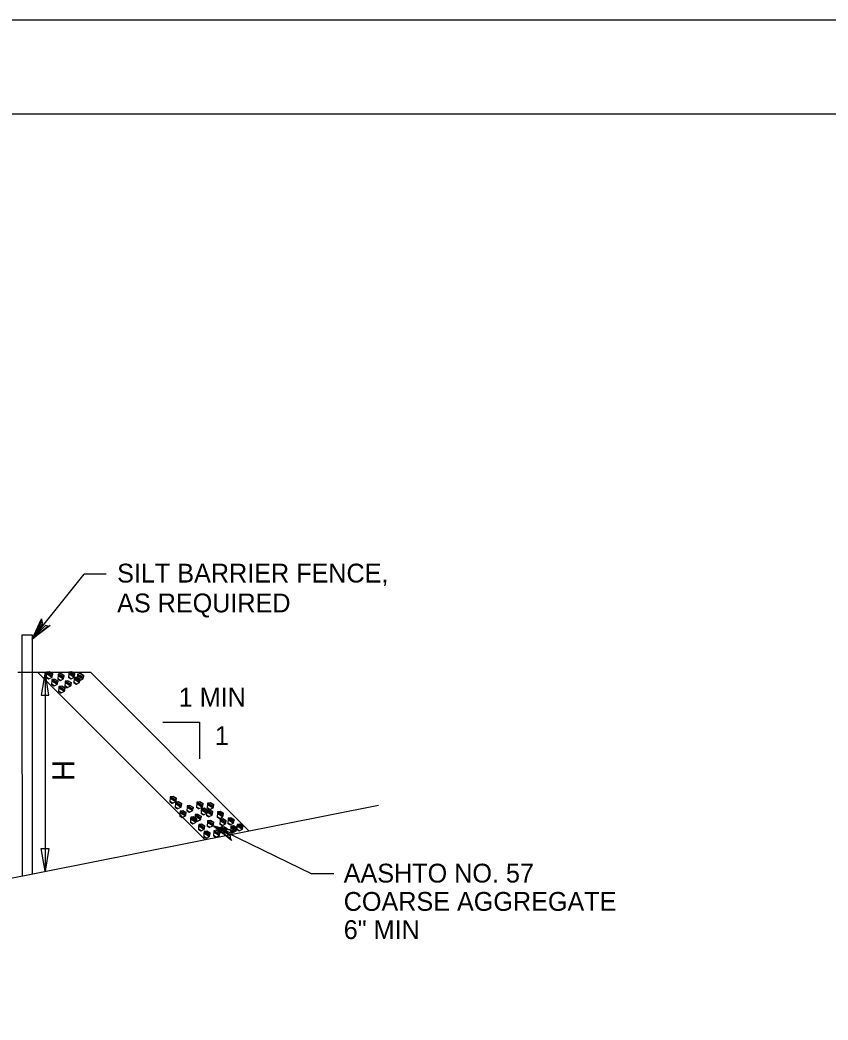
# Model space of a CAD drawing. Extents: x 636462 to 639049, y 299944 to 300538.
# Drawn here: x 637774 to 637902.8, y 300379.2 to 300538.4 of the extents above; entities that cross this region are included whole.
import ezdxf

# ---------------------------------------------------------------- set-up
doc = ezdxf.new("R2010")
doc.units = 0
for name, color, linetype in [('1', 7, 'Continuous'), ('Default', 7, 'Continuous'), ('PLT-BNDY', 7, 'Continuous')]:
    doc.layers.add(name, color=color, linetype=linetype)

msp = doc.modelspace()

# ---------------------------------------------------------------- linework, layer by layer
at = {"layer": '1'}
msp.add_lwpolyline([(638128.91, 299959.45), (638128.91, 300523.45), (637342.91, 300523.45), (637342.91, 299959.45), (638128.91, 299959.45), (638128.91, 299985.81), (637928.91, 299985.81), (637928.91, 300050.49), (638128.91, 300050.49), (638128.91, 300079.45), (637928.91, 300079.45), (637928.91, 299959.45), (638007.72, 299959.45), (638007.72, 299985.81), (638007.72, 299959.45), (638084.72, 299959.45), (638084.72, 299985.81), (638084.72, 299973.49), (638128.91, 299973.49)], dxfattribs=at)
at = {"layer": 'Default'}
for p, q in [((637775.96, 300439.85), (637784.28, 300450.2)), ((637787.77, 300450.2), (637784.28, 300450.2)), ((637774.37, 300440.54), (637775.96, 300440.54)), ((637774.38, 300434.62), (637774.37, 300440.54)), ((637775.96, 300440.54), (637775.96, 300434.66)), ((637773.72, 300434.6), (637785.25, 300434.6)), ((637774.47, 300402.15), (637774.38, 300434.54)), ((637775.96, 300434.55), (637775.96, 300402.48)), ((637776.84, 300434.6), (637803.49, 300407.95)), ((637778.04, 300434.6), (637778.04, 300402.9)), ((637785.25, 300434.6), (637810.51, 300409.34)), ((637718.2, 300391.02), (637831.16, 300413.44)), ((637804.92, 300410.07), (637820.54, 300402.49)), ((637824.04, 300402.49), (637820.54, 300402.49))]:
    msp.add_line(p, q, dxfattribs=at)
for points in [[(637778.5, 300441.95), (637778.84, 300442.02), (637775.96, 300439.85), (637778.5, 300441.95), (637778.09, 300442.03), (637775.96, 300439.85), (637777.68, 300442.36), (637777.5, 300442.74), (637775.96, 300439.85), (637777.48, 300443.12), (637777.5, 300442.74)], [(637796.8, 300426.66), (637802.64, 300426.66), (637802.64, 300420.82)], [(637807.57, 300408.11), (637807.71, 300407.79), (637804.92, 300410.07), (637807.57, 300408.11), (637807.55, 300408.53), (637804.92, 300410.07), (637807.77, 300409), (637808.09, 300409.27), (637804.92, 300410.07), (637808.46, 300409.37), (637808.09, 300409.27)]]:
    msp.add_lwpolyline(points, dxfattribs=at)
for points in [[(637777.43, 300430.96), (637778.64, 300430.96), (637778.04, 300434.6)], [(637778.21, 300433.83), (637778.63, 300433.57), (637779.15, 300433.83), (637778.25, 300434.39)], [(637778.6, 300433.56), (637778.6, 300433.56), (637778.63, 300433.57), (637778.21, 300433.83)], [(637778.25, 300434.39), (637779.15, 300433.83), (637779.19, 300434.03), (637778.27, 300434.6)], [(637778.27, 300434.6), (637779.19, 300434.03), (637779.25, 300434.31), (637778.7, 300434.65)], [(637778.7, 300434.65), (637779.25, 300434.31), (637779.26, 300434.33), (637779.26, 300434.33)], [(637779.11, 300433.25), (637780, 300432.7), (637780.04, 300432.89), (637779.12, 300433.46)], [(637779.12, 300433.46), (637780.04, 300432.89), (637780.1, 300433.18), (637779.56, 300433.52)], [(637779.56, 300433.52), (637780.1, 300433.18), (637780.11, 300433.19), (637780.11, 300433.19)], [(637780.06, 300433.55), (637780.48, 300433.29), (637780.99, 300433.55), (637780.1, 300434.1)], [(637780.44, 300433.27), (637780.44, 300433.27), (637780.48, 300433.29), (637780.06, 300433.55)], [(637780.1, 300434.1), (637780.99, 300433.55), (637781.03, 300433.74), (637780.11, 300434.31)], [(637780.11, 300434.31), (637781.03, 300433.74), (637781.1, 300434.03), (637780.55, 300434.37)], [(637780.55, 300434.37), (637781.1, 300434.03), (637781.1, 300434.04), (637781.1, 300434.04)], [(637781.76, 300433.83), (637782.17, 300433.57), (637782.69, 300433.83), (637781.8, 300434.38)], [(637782.14, 300433.56), (637782.14, 300433.56), (637782.17, 300433.57), (637781.76, 300433.83)], [(637781.8, 300434.38), (637782.69, 300433.83), (637782.73, 300434.03), (637781.81, 300434.6)], [(637781.81, 300434.6), (637782.73, 300434.03), (637782.8, 300434.31), (637782.25, 300434.65)], [(637782.25, 300434.65), (637782.8, 300434.31), (637782.8, 300434.33), (637782.8, 300434.33)], [(637782.61, 300432.98), (637783.03, 300432.72), (637783.54, 300432.98), (637782.65, 300433.54)], [(637782.65, 300433.54), (637783.54, 300432.98), (637783.59, 300433.18), (637782.66, 300433.75)], [(637782.66, 300433.75), (637783.59, 300433.18), (637783.65, 300433.46), (637783.1, 300433.8)], [(637783.1, 300433.8), (637783.65, 300433.46), (637783.65, 300433.47), (637783.65, 300433.47)], [(637783.18, 300433.55), (637783.59, 300433.29), (637784.11, 300433.55), (637783.21, 300434.1)], [(637783.56, 300433.27), (637783.56, 300433.27), (637783.59, 300433.29), (637783.18, 300433.55)], [(637783.21, 300434.1), (637784.11, 300433.55), (637784.15, 300433.74), (637783.23, 300434.31)], [(637783.23, 300434.31), (637784.15, 300433.74), (637784.22, 300434.03), (637783.67, 300434.37)], [(637783.67, 300434.37), (637784.22, 300434.03), (637784.22, 300434.04), (637784.22, 300434.04)], [(637779.07, 300432.7), (637779.48, 300432.44), (637780, 300432.7), (637779.11, 300433.25)], [(637779.45, 300432.42), (637779.45, 300432.42), (637779.48, 300432.44), (637779.07, 300432.7)], [(637780.2, 300431.57), (637780.62, 300431.31), (637781.13, 300431.57), (637780.24, 300432.12)], [(637780.24, 300432.12), (637781.13, 300431.57), (637781.17, 300431.76), (637780.25, 300432.33)], [(637780.25, 300432.33), (637781.17, 300431.76), (637781.24, 300432.05), (637780.69, 300432.39)], [(637780.69, 300432.39), (637781.24, 300432.05), (637781.24, 300432.05), (637781.24, 300432.05)], [(637781.2, 300432.42), (637781.61, 300432.16), (637782.13, 300432.42), (637781.23, 300432.97)], [(637781.57, 300432.14), (637781.57, 300432.14), (637781.61, 300432.16), (637781.2, 300432.42)], [(637781.23, 300432.97), (637782.13, 300432.42), (637782.17, 300432.61), (637781.24, 300433.18)], [(637781.24, 300433.18), (637782.17, 300432.61), (637782.23, 300432.9), (637781.68, 300433.24)], [(637781.68, 300433.24), (637782.23, 300432.9), (637782.23, 300432.91), (637782.23, 300432.91)], [(637782.99, 300432.71), (637782.99, 300432.71), (637783.03, 300432.72), (637782.61, 300432.98)], [(637780.58, 300431.29), (637780.58, 300431.29), (637780.62, 300431.31), (637780.2, 300431.57)], [(637797.93, 300414), (637798.35, 300413.73), (637798.86, 300414), (637797.97, 300414.55)], [(637797.97, 300414.55), (637798.86, 300414), (637798.9, 300414.19), (637797.98, 300414.76)], [(637797.98, 300414.76), (637798.9, 300414.19), (637798.96, 300414.47), (637798.42, 300414.81)], [(637798.42, 300414.81), (637798.96, 300414.47), (637798.97, 300414.48), (637798.97, 300414.48)], [(637798.31, 300413.72), (637798.31, 300413.72), (637798.35, 300413.73), (637797.93, 300414)], [(637798.77, 300413.14), (637799.19, 300412.88), (637799.71, 300413.14), (637798.82, 300413.69)], [(637799.16, 300412.86), (637799.16, 300412.86), (637799.19, 300412.88), (637798.77, 300413.14)], [(637798.82, 300413.69), (637799.71, 300413.14), (637799.75, 300413.33), (637798.83, 300413.9)], [(637798.83, 300413.9), (637799.75, 300413.33), (637799.81, 300413.62), (637799.27, 300413.96)], [(637799.27, 300413.96), (637799.81, 300413.62), (637799.82, 300413.63), (637799.82, 300413.63)], [(637800.62, 300412.58), (637801.04, 300412.32), (637801.55, 300412.58), (637800.66, 300413.13)], [(637800.66, 300413.13), (637801.55, 300412.58), (637801.6, 300412.77), (637800.67, 300413.34)], [(637800.67, 300413.34), (637801.6, 300412.77), (637801.66, 300413.06), (637801.11, 300413.39)], [(637801.11, 300413.39), (637801.66, 300413.06), (637801.66, 300413.06), (637801.66, 300413.06)], [(637802.18, 300413.14), (637802.6, 300412.88), (637803.11, 300413.14), (637802.22, 300413.69)], [(637802.56, 300412.86), (637802.56, 300412.86), (637802.6, 300412.88), (637802.18, 300413.14)], [(637802.22, 300413.69), (637803.11, 300413.14), (637803.16, 300413.33), (637802.24, 300413.9)], [(637802.24, 300413.9), (637803.16, 300413.33), (637803.22, 300413.62), (637802.68, 300413.96)], [(637802.68, 300413.96), (637803.22, 300413.62), (637803.22, 300413.63), (637803.22, 300413.63)], [(637802.89, 300412.14), (637803.3, 300411.89), (637803.82, 300412.14), (637802.93, 300412.7)], [(637802.93, 300412.7), (637803.82, 300412.14), (637803.87, 300412.34), (637802.94, 300412.92)], [(637802.94, 300412.92), (637803.87, 300412.34), (637803.93, 300412.63), (637803.38, 300412.97)], [(637803.38, 300412.97), (637803.93, 300412.63), (637803.93, 300412.64), (637803.93, 300412.64)], [(637803.78, 300412.41), (637804.67, 300411.86), (637804.71, 300412.06), (637803.8, 300412.63)], [(637803.8, 300412.63), (637804.71, 300412.06), (637804.78, 300412.35), (637804.23, 300412.69)], [(637803.88, 300413), (637804.3, 300412.74), (637804.81, 300413), (637803.92, 300413.56)], [(637804.27, 300412.72), (637804.27, 300412.72), (637804.3, 300412.74), (637803.88, 300413)], [(637803.92, 300413.56), (637804.81, 300413), (637804.86, 300413.19), (637803.93, 300413.76)], [(637803.93, 300413.76), (637804.86, 300413.19), (637804.92, 300413.48), (637804.37, 300413.82)], [(637804.23, 300412.69), (637804.78, 300412.35), (637804.78, 300412.36), (637804.78, 300412.36)], [(637804.37, 300413.82), (637804.92, 300413.48), (637804.92, 300413.49), (637804.92, 300413.49)], [(637799.49, 300411.72), (637799.9, 300411.46), (637800.42, 300411.72), (637799.52, 300412.28)], [(637799.87, 300411.45), (637799.87, 300411.45), (637799.9, 300411.46), (637799.49, 300411.72)], [(637799.52, 300412.28), (637800.42, 300411.72), (637800.46, 300411.91), (637799.54, 300412.49)], [(637799.54, 300412.49), (637800.46, 300411.91), (637800.53, 300412.2), (637799.98, 300412.54)], [(637799.98, 300412.54), (637800.53, 300412.2), (637800.53, 300412.22), (637800.53, 300412.22)], [(637801, 300412.3), (637801, 300412.3), (637801.04, 300412.32), (637800.62, 300412.58)], [(637801.19, 300410.73), (637801.6, 300410.47), (637802.12, 300410.73), (637801.23, 300411.28)], [(637801.23, 300411.28), (637802.12, 300410.73), (637802.16, 300410.93), (637801.24, 300411.5)], [(637801.24, 300411.5), (637802.16, 300410.93), (637802.23, 300411.21), (637801.68, 300411.55)], [(637801.68, 300411.55), (637802.23, 300411.21), (637802.23, 300411.22), (637802.23, 300411.22)], [(637801.89, 300411.16), (637802.31, 300410.9), (637802.83, 300411.16), (637801.94, 300411.71)], [(637802.28, 300410.88), (637802.28, 300410.88), (637802.31, 300410.9), (637801.89, 300411.16)], [(637801.94, 300411.71), (637802.83, 300411.16), (637802.87, 300411.35), (637801.95, 300411.92)], [(637801.95, 300411.92), (637802.87, 300411.35), (637802.94, 300411.63), (637802.39, 300411.97)], [(637802.39, 300411.97), (637802.94, 300411.63), (637802.94, 300411.65), (637802.94, 300411.65)], [(637803.27, 300411.87), (637803.27, 300411.87), (637803.3, 300411.89), (637802.89, 300412.14)], [(637803.74, 300411.86), (637804.16, 300411.61), (637804.67, 300411.86), (637803.78, 300412.41)], [(637804.13, 300411.59), (637804.13, 300411.59), (637804.16, 300411.61), (637803.74, 300411.86)], [(637805.44, 300411.58), (637805.86, 300411.33), (637806.38, 300411.58), (637805.48, 300412.14)], [(637805.82, 300411.31), (637805.82, 300411.31), (637805.86, 300411.33), (637805.44, 300411.58)], [(637805.48, 300412.14), (637806.38, 300411.58), (637806.42, 300411.78), (637805.5, 300412.35)], [(637805.5, 300412.35), (637806.42, 300411.78), (637806.48, 300412.06), (637805.93, 300412.4)], [(637805.91, 300411), (637806.8, 300410.45), (637806.84, 300410.64), (637805.92, 300411.21)], [(637805.92, 300411.21), (637806.84, 300410.64), (637806.91, 300410.93), (637806.36, 300411.27)], [(637805.93, 300412.4), (637806.48, 300412.06), (637806.48, 300412.08), (637806.48, 300412.08)], [(637806.36, 300411.27), (637806.91, 300410.93), (637806.91, 300410.94), (637806.91, 300410.94)], [(637807.15, 300410.59), (637807.56, 300410.33), (637808.08, 300410.59), (637807.18, 300411.14)], [(637807.18, 300411.14), (637808.08, 300410.59), (637808.12, 300410.79), (637807.2, 300411.36)], [(637807.2, 300411.36), (637808.12, 300410.79), (637808.18, 300411.07), (637807.64, 300411.41)], [(637807.64, 300411.41), (637808.18, 300411.07), (637808.19, 300411.08), (637808.19, 300411.08)], [(637801.57, 300410.46), (637801.57, 300410.46), (637801.6, 300410.47), (637801.19, 300410.73)], [(637802.46, 300409.6), (637802.88, 300409.34), (637803.4, 300409.6), (637802.5, 300410.15)], [(637802.85, 300409.33), (637802.85, 300409.33), (637802.88, 300409.34), (637802.46, 300409.6)], [(637802.5, 300410.15), (637803.4, 300409.6), (637803.44, 300409.79), (637802.52, 300410.37)], [(637802.52, 300410.37), (637803.44, 300409.79), (637803.5, 300410.08), (637802.96, 300410.42)], [(637802.96, 300410.42), (637803.5, 300410.08), (637803.51, 300410.09), (637803.51, 300410.09)], [(637803.88, 300410.16), (637804.29, 300409.91), (637804.81, 300410.16), (637803.92, 300410.72)], [(637804.27, 300409.89), (637804.27, 300409.89), (637804.29, 300409.91), (637803.88, 300410.16)], [(637803.92, 300410.72), (637804.81, 300410.16), (637804.86, 300410.36), (637803.93, 300410.93)], [(637803.93, 300410.93), (637804.86, 300410.36), (637804.92, 300410.65), (637804.37, 300410.99)], [(637804.09, 300410.47), (637804.09, 300410.47), (637804.09, 300410.47)], [(637804.37, 300410.99), (637804.92, 300410.65), (637804.92, 300410.65), (637804.92, 300410.65)], [(637804.93, 300409.37), (637805.85, 300408.8), (637805.91, 300409.09), (637805.37, 300409.43)], [(637805.37, 300409.43), (637805.91, 300409.09), (637805.92, 300409.1), (637805.92, 300409.1)], [(637805.87, 300410.45), (637806.28, 300410.19), (637806.8, 300410.45), (637805.91, 300411)], [(637806.25, 300410.17), (637806.25, 300410.17), (637806.28, 300410.19), (637805.87, 300410.45)], [(637806.01, 300409.17), (637806.42, 300408.92), (637806.94, 300409.17), (637806.05, 300409.72)], [(637806.05, 300409.72), (637806.94, 300409.17), (637806.98, 300409.37), (637806.06, 300409.94)], [(637806.06, 300409.94), (637806.98, 300409.37), (637807.05, 300409.66), (637806.5, 300410)], [(637806.5, 300410), (637807.05, 300409.66), (637807.05, 300409.66), (637807.05, 300409.66)], [(637807.53, 300410.32), (637807.53, 300410.32), (637807.56, 300410.33), (637807.15, 300410.59)], [(637807.57, 300409.32), (637807.99, 300409.06), (637808.5, 300409.32), (637807.61, 300409.87)], [(637807.61, 300409.87), (637808.5, 300409.32), (637808.54, 300409.51), (637807.63, 300410.08)], [(637807.63, 300410.08), (637808.54, 300409.51), (637808.61, 300409.79), (637808.06, 300410.13)], [(637808.06, 300410.13), (637808.61, 300409.79), (637808.61, 300409.8), (637808.61, 300409.8)], [(637808.56, 300409.6), (637808.98, 300409.34), (637809.49, 300409.6), (637808.6, 300410.15)], [(637808.95, 300409.33), (637808.95, 300409.33), (637808.98, 300409.34), (637808.56, 300409.6)], [(637808.6, 300410.15), (637809.49, 300409.6), (637809.54, 300409.8), (637808.62, 300410.37)], [(637808.62, 300410.37), (637809.54, 300409.8), (637809.6, 300410.08), (637809.05, 300410.42)], [(637809.05, 300410.42), (637809.6, 300410.08), (637809.61, 300410.09), (637809.61, 300410.09)], [(637803.32, 300408.46), (637803.73, 300408.2), (637804.25, 300408.46), (637803.35, 300409.01)], [(637803.7, 300408.19), (637803.7, 300408.19), (637803.73, 300408.2), (637803.32, 300408.46)], [(637803.35, 300409.01), (637804.25, 300408.46), (637804.29, 300408.66), (637803.37, 300409.23)], [(637803.37, 300409.23), (637804.29, 300408.66), (637804.35, 300408.94), (637803.81, 300409.28)], [(637803.81, 300409.28), (637804.35, 300408.94), (637804.36, 300408.96), (637804.36, 300408.96)], [(637804.87, 300408.6), (637805.29, 300408.35), (637805.81, 300408.6), (637804.91, 300409.16)], [(637805.26, 300408.33), (637805.26, 300408.33), (637805.29, 300408.35), (637804.87, 300408.6)], [(637804.91, 300409.16), (637805.81, 300408.6), (637805.85, 300408.8), (637804.93, 300409.37)], [(637806.39, 300408.9), (637806.39, 300408.9), (637806.42, 300408.92), (637806.01, 300409.17)], [(637807.95, 300409.04), (637807.95, 300409.04), (637807.99, 300409.06), (637807.57, 300409.32)], [(637777.43, 300406.54), (637778.64, 300406.54), (637778.04, 300402.9)]]:
    msp.add_lwpolyline(points, close=True, dxfattribs=at)
at = {"layer": 'PLT-BNDY'}
msp.add_lwpolyline([(637302.91, 300538.45), (638143.91, 300538.45), (638143.91, 299944.45), (637302.91, 299944.45)], close=True, dxfattribs=at)

# ---------------------------------------------------------------- texts
at = {"layer": 'Default'}
for s, height, p in [('SILT BARRIER FENCE,', 2.998, (637789.52, 300448.88)), ('AS REQUIRED', 2.998, (637789.52, 300444.13)), ('1 MIN', 2.998, (637799.33, 300429.13)), ('1', 3, (637805.09, 300423)), ('AASHTO NO. 57', 2.998, (637825.61, 300401.11)), ('COARSE AGGREGATE', 2.998, (637825.61, 300396.61)), ('6" MIN', 2.998, (637825.61, 300392.12))]:
    msp.add_text(s, height=height, dxfattribs=at).set_placement(p)
msp.add_text('H', height=3.5, rotation=90, dxfattribs=at).set_placement((637782.72, 300417.27))

doc.saveas('drawing.dxf')
